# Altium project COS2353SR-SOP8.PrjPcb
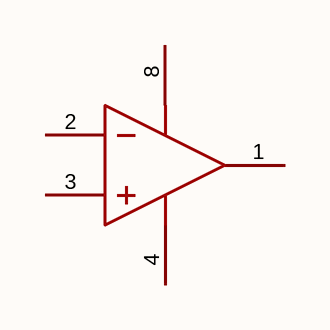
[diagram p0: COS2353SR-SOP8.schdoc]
1 sheet, 1 parts. Net scope: global (net labels, ports and power ports of the same name join across sheets).

## Sheet COS2353SR-SOP8.schdoc
size 127 x 101 mm

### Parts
U?  cos2353sr  [SOP-8_L4.9-W3.9-P1.27-LS6.0-BL]  (value not drawn)  (part A of 2)

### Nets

Not connected (* = marked no-connect by the designer): U? 1(OUT_A) 2(-IN_A) 3(+IN_A) 4(-VS) 8(+VS)

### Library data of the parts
U? = cos2353sr: 放大器数:2;轨到轨:轨到轨输入,轨到轨输出;增益带宽积(GBW):50MHz;输入失调电压(Vos):600uV;压摆率(SR):38V/us;输入偏置电流(Ib):2.5pA;; Manufacturer: COSINE(科山芯创); Symbol: COS2353SR-SOP8; AddInBom: yes; ModelId: 75c24a7891ee4dd6bdac16a7163ff87e; ModelName: SOP-8_L4.9-W3.9-P1.27-LS6.0-BL-1; ModelTransform: 192.913,236.22,0,0,0,0,-0.393,2.749,0; Number of Channels: 2; Gain Bandwidth Product: 50MHz; Vos - Input Offset Voltage: 600uV; Input Offset Voltage Drift(Vos TC): 2uV/℃; Slew Rate: 38V/us; Ib - Input Bias Current: 2.5pA; Input Voltage Noise Density: 8nV/√Hz@1kHz; Common Mode Rejection Ratio(CMRR): 125dB; Quiescent Current: 2.5mA; Output Current: 100mA; Single supply: 2.5V~5.5V; Dual Supply: -2.25V~2.25V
